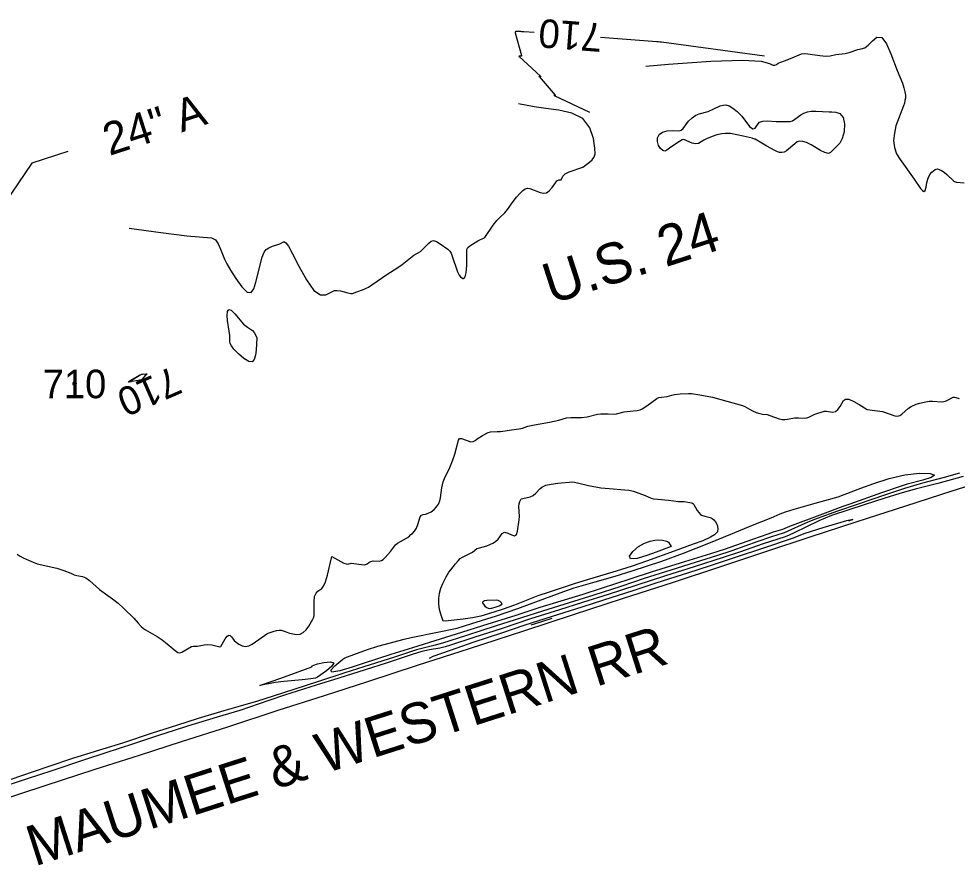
# Model space of a CAD drawing. Extents: x -468541894 to 3393103, y -306086142 to 1227927.
# Drawn here: x 1843544 to 1844629, y 537989 to 538967 of the extents above; entities that cross this region are included whole.
import ezdxf

# ---------------------------------------------------------------- set-up
doc = ezdxf.new("R2010")
doc.units = 0
for name, color, linetype in [('DT_X_Contour_Minor', 7, 'Continuous'), ('Level 14', 7, 'Continuous'), ('Level 19', 7, 'Continuous'), ('Level 40', 7, 'Continuous')]:
    doc.layers.add(name, color=color, linetype=linetype)

msp = doc.modelspace()

# ---------------------------------------------------------------- linework, layer by layer
at = {"layer": 'DT_X_Contour_Minor'}
for points in [[(1844140.1, 538951.4), (1844128.5, 538952.2), (1844127.3, 538952.3), (1844126.1, 538952.4), (1844124.8, 538952.5), (1844123.6, 538952.5), (1844119.6, 538952.7), (1844118.9, 538952.7), (1844118.4, 538952.4), (1844118.2, 538951.9), (1844118.3, 538951.2), (1844125.7, 538925), (1844125.8, 538924.5), (1844125.7, 538924.2), (1844125.4, 538924), (1844124.9, 538924), (1844123, 538924.2), (1844122.6, 538924.2), (1844122.5, 538924.1), (1844122.5, 538923.9), (1844122.8, 538923.7), (1844147.6, 538901.1), (1844147.8, 538900.8), (1844147.8, 538900.7), (1844147.7, 538900.6), (1844147.4, 538900.6), (1844146.1, 538900.8), (1844145.9, 538900.8), (1844145.8, 538900.7), (1844145.8, 538900.6), (1844145.9, 538900.4), (1844164.5, 538879.1), (1844164.6, 538878.9), (1844164.6, 538878.8), (1844164.5, 538878.8), (1844164.3, 538878.8), (1844163.4, 538878.9), (1844163.3, 538878.9), (1844163.2, 538878.9), (1844163.3, 538878.9), (1844163.4, 538878.8), (1844204.1, 538859.5)], [(1844406.7, 538924.2), (1844287.5, 538940.2), (1844287, 538940.3), (1844286.5, 538940.3), (1844286, 538940.4), (1844285.4, 538940.4), (1844283.7, 538940.5), (1844283.3, 538940.5), (1844282.9, 538940.6), (1844282.6, 538940.6), (1844282.2, 538940.6), (1844217.1, 538945.5)], [(1844269.3, 538912.4), (1844295.5, 538914.7), (1844344.6, 538918.3), (1844381.3, 538919.6), (1844402.7, 538918.3), (1844412.5, 538915.7), (1844416.3, 538913.7), (1844418.6, 538913.5), (1844420.6, 538914.5), (1844422.4, 538915.9), (1844424.3, 538916.9), (1844430.7, 538919), (1844441.4, 538923.3), (1844449.5, 538926.7), (1844452.4, 538927.1), (1844456.6, 538926.7), (1844470.7, 538924.7), (1844477.6, 538924.1), (1844482.6, 538924.5), (1844488.9, 538926.2), (1844499.8, 538927), (1844504.6, 538928.4), (1844514.3, 538931.9), (1844518.5, 538932.7), (1844522.4, 538933.9), (1844526.6, 538936.7), (1844531.4, 538941.8), (1844536.6, 538946.1), (1844542.2, 538945.8), (1844547.7, 538938.4), (1844552.8, 538926.8), (1844560.1, 538907.5), (1844566, 538892.9), (1844567.7, 538887.6), (1844568.9, 538882.8), (1844569.4, 538878.9), (1844569.4, 538875.6), (1844569, 538872.8), (1844568.3, 538869.9), (1844567.3, 538866.6), (1844558.6, 538843.5), (1844556.7, 538835.2), (1844555.9, 538826.7), (1844556.7, 538818.5), (1844559.3, 538811.2), (1844563.3, 538804.7), (1844579.7, 538782), (1844587.1, 538771), (1844589.1, 538768.7), (1844590.8, 538767.7), (1844592.3, 538768.9), (1844593.3, 538772.6), (1844594.4, 538777.9), (1844595.8, 538783.1), (1844597.9, 538787.1), (1844600.2, 538789.9), (1844603.9, 538792.9), (1844605.2, 538793.6), (1844606.7, 538793.7), (1844608.7, 538793.2), (1844611.3, 538792), (1844614.3, 538790.1), (1844617.4, 538787.2), (1844625, 538779.8), (1844626.4, 538779), (1844628.5, 538778.5), (1844637.5, 538777.8)], [(1844209.4, 538806.8), (1844210.7, 538810.8), (1844210.6, 538817.8), (1844209, 538828.8), (1844204.7, 538841.2), (1844196.6, 538851.9), (1844184, 538858.3), (1844168.8, 538861.5), (1844153.6, 538863.4), (1844140.1, 538865.5), (1844122.3, 538869.1)], [(1844395.8, 538828.2), (1844395.2, 538828.1), (1844392.3, 538829.1), (1844382.1, 538831.7), (1844374.4, 538833.3), (1844367.1, 538834.5), (1844361.5, 538834.8), (1844357.4, 538834.4), (1844351.5, 538833), (1844346.1, 538831.4), (1844339.6, 538828.7), (1844336.4, 538826.9), (1844333.3, 538824.9), (1844330.2, 538823.3), (1844326.8, 538822.7), (1844322.8, 538823.7), (1844313.2, 538827.6), (1844311.2, 538827.2), (1844305.1, 538823.4), (1844296.9, 538817.8), (1844293.8, 538815.6), (1844291.3, 538814.4), (1844289, 538814.9), (1844286.4, 538817.2), (1844284.1, 538821), (1844282.8, 538825.4), (1844283, 538829.8), (1844284.9, 538833.5), (1844288.6, 538836.3), (1844293.9, 538837.6), (1844299.8, 538838), (1844308.2, 538837.9), (1844310.3, 538838.5), (1844312.4, 538840.5), (1844318.8, 538848.8), (1844322.8, 538852.9), (1844327.1, 538855.8), (1844331.2, 538857.5), (1844341.4, 538860.3), (1844348.1, 538863.2), (1844355.3, 538866.5), (1844358.6, 538867.6), (1844361.9, 538867.8), (1844365.6, 538866.7), (1844370.1, 538864.1), (1844375.1, 538860), (1844380.2, 538854.6), (1844389.4, 538842.9), (1844392.9, 538840), (1844395.6, 538841), (1844398, 538844.3), (1844400.8, 538847.6), (1844404.7, 538849.1), (1844409.5, 538849.3), (1844420.2, 538848.7), (1844436.1, 538848.6), (1844438.8, 538849.4), (1844441.8, 538851.3), (1844448.5, 538856.3), (1844452.1, 538858.3), (1844456.1, 538859.8), (1844460.6, 538860.5), (1844465.9, 538860.6), (1844481.3, 538859.9), (1844484.5, 538859.9), (1844489, 538859.5), (1844493.7, 538857.7), (1844497.4, 538853.3), (1844499, 538845.8), (1844498.5, 538836.8), (1844496.5, 538828.9), (1844493.5, 538823.6), (1844485, 538815), (1844483, 538812.6), (1844480.4, 538811.6), (1844476.3, 538812.6), (1844471.3, 538815.2), (1844460.4, 538821.5), (1844455.3, 538824.1), (1844450.9, 538825.6), (1844447.5, 538825.9), (1844444.5, 538824.9), (1844441.7, 538822.8), (1844432.1, 538814.5), (1844429.3, 538813), (1844426.6, 538812.6), (1844424.1, 538812.8), (1844421.5, 538813.6), (1844418.5, 538815), (1844409.2, 538820.2), (1844395.8, 538828.2)], [(1843671.9, 538725.3), (1843708.5, 538720.3), (1843738.9, 538716.5), (1843767.1, 538713.9), (1843771.7, 538711.8), (1843775, 538707.3), (1843777.7, 538701.1), (1843782.3, 538689.5), (1843785.1, 538684), (1843789.3, 538676.8), (1843795.4, 538667.2), (1843802.3, 538657.6), (1843808.5, 538651.3), (1843813, 538650.7), (1843816, 538655), (1843818.5, 538662.9), (1843826, 538691.6), (1843828.1, 538697.3), (1843830.4, 538700.6), (1843833.5, 538702.6), (1843837.8, 538704.3), (1843846.4, 538707.2), (1843850.5, 538709.4), (1843851.7, 538709.6), (1843853.3, 538708.4), (1843856.1, 538704.3), (1843860.9, 538695.5), (1843868.2, 538681.2), (1843876.9, 538665.4), (1843885.7, 538653.1), (1843893.4, 538648), (1843899.5, 538648.3), (1843909.6, 538653.3), (1843912.4, 538653.3), (1843916.5, 538652.6), (1843924.7, 538650.5), (1843928.5, 538649.6), (1843930.1, 538649.8), (1843935.4, 538651.5), (1843941.9, 538654.1), (1843948.6, 538657.2), (1843952.6, 538659.8), (1843971.1, 538672.3), (1843981.5, 538679), (1843987.6, 538683.3), (1844001.2, 538693.9), (1844008.8, 538698.3), (1844015.3, 538704.8), (1844018.6, 538708), (1844021.2, 538710.1), (1844023.9, 538710.8), (1844027.2, 538709.8), (1844031.7, 538707.3), (1844040.4, 538700.9), (1844042.9, 538698.6), (1844044.3, 538696.4), (1844047.4, 538687.1), (1844049.6, 538680.5), (1844051.8, 538674.7), (1844053.7, 538670.9), (1844055.3, 538668.9), (1844057.7, 538667.2), (1844058.6, 538667), (1844059.5, 538667.5), (1844060.4, 538669.1), (1844061.2, 538672), (1844061.9, 538676.8), (1844062.3, 538683.4), (1844062.6, 538700.6), (1844063.4, 538702.9), (1844065.8, 538705), (1844075.2, 538710.4), (1844083.2, 538714.6), (1844092.9, 538728.8), (1844097.1, 538734), (1844100.6, 538737.6), (1844106.4, 538742.9), (1844109.4, 538746.7), (1844116.1, 538756.2), (1844120, 538761.1), (1844123.9, 538765.4), (1844127.3, 538768.7), (1844130, 538770.7), (1844132.5, 538771.4), (1844135.3, 538771), (1844147.3, 538766.4), (1844151, 538765.7), (1844154.5, 538766.2), (1844157.8, 538768.4), (1844161, 538772.3), (1844164, 538776.6), (1844166.6, 538779.9), (1844168.8, 538781.1), (1844171.6, 538781.3), (1844173.5, 538785.3), (1844176.2, 538787.9), (1844180.9, 538790.3), (1844196.5, 538795.6), (1844204.1, 538801.6), (1844207.2, 538804.2), (1844209.4, 538806.8)], [(1843819.6, 538598.3), (1843818.7, 538584.2), (1843818, 538578.3), (1843816.6, 538573.5), (1843814.3, 538570.8), (1843810.3, 538571), (1843804.6, 538574.6), (1843798.4, 538580.1), (1843793.2, 538585.4), (1843790.2, 538589.1), (1843789, 538591.7), (1843788.6, 538594.1), (1843788.3, 538601.1), (1843787.7, 538606.1), (1843785.8, 538618.3), (1843785.3, 538624.2), (1843785.6, 538628.8), (1843787.1, 538631.2), (1843790, 538630.5), (1843794.3, 538626.3), (1843804.4, 538614.4), (1843808.7, 538610.7), (1843814.8, 538606.8), (1843816.7, 538604.5), (1843818.1, 538602), (1843819.6, 538598.3)], [(1843673.4, 538549), (1843683.9, 538555.2), (1843684.2, 538555.4), (1843684.5, 538555.5), (1843684.8, 538555.7), (1843685.2, 538555.8), (1843686.2, 538556.3), (1843686.4, 538556.4), (1843686.6, 538556.5), (1843686.9, 538556.5), (1843687.1, 538556.6), (1843691.4, 538557), (1843692.1, 538557), (1843692.5, 538556.8), (1843692.4, 538556.4), (1843691.9, 538555.9), (1843690.5, 538554.4)], [(1843686.2, 538549.9), (1843679.8, 538548.6), (1843676.2, 538548.1), (1843674.4, 538548.5), (1843675.6, 538550), (1843682.3, 538554.2), (1843686.1, 538556.1), (1843689, 538556.7), (1843690.4, 538556.6), (1843691.1, 538556), (1843690.6, 538554.8), (1843687, 538550.8), (1843686.2, 538549.9)], [(1843607.5, 538546.9), (1843606.9, 538544.8), (1843606.9, 538544.5), (1843607, 538544.4), (1843607.1, 538544.3), (1843607.4, 538544.3), (1843608.3, 538544.3), (1843608.5, 538544.3), (1843608.7, 538544.3), (1843608.8, 538544.3), (1843609, 538544.2), (1843609.7, 538544.2), (1843609.9, 538544.2), (1843610, 538544.2), (1843610.1, 538544.3), (1843610.2, 538544.4), (1843611.2, 538545.5), (1843611.3, 538545.7), (1843611.3, 538545.9), (1843611.2, 538546.1), (1843611, 538546.2), (1843608.3, 538547.2), (1843608.2, 538547.2), (1843608.2, 538547.2), (1843608.1, 538547.2), (1843608, 538547.2), (1843607.7, 538547.1), (1843607.6, 538547.1), (1843607.6, 538547), (1843607.6, 538547), (1843607.5, 538546.9)], [(1843608.2, 538547.3), (1843610.2, 538546.4), (1843610.7, 538545.9), (1843610.8, 538545.4), (1843610, 538544.5), (1843609.1, 538544.2), (1843607.5, 538544.4), (1843607.2, 538544.7), (1843607.3, 538546), (1843607.9, 538547.2), (1843608.2, 538547.3)], [(1843674.7, 538547.5), (1843674, 538547.4), (1843672, 538547.1), (1843671.3, 538547.2), (1843671.7, 538547.9), (1843673.4, 538549)], [(1844213.4, 538510.2), (1844217.4, 538510.5), (1844225.8, 538510.4), (1844232.6, 538510.2), (1844235.4, 538510.4), (1844244.5, 538512.9), (1844254.8, 538514.1), (1844259.4, 538514.6), (1844262.7, 538515.3), (1844265.2, 538516.3), (1844270.7, 538519.9), (1844282.1, 538528.4), (1844284.5, 538529.5), (1844287.4, 538530), (1844293.9, 538530.6), (1844299.5, 538532.1), (1844302.4, 538532.9), (1844309.2, 538533.7), (1844318.6, 538534.2), (1844322.3, 538534), (1844331.9, 538532.4), (1844346.5, 538529.8), (1844362.9, 538525.4), (1844381.2, 538520.4), (1844384, 538519.1), (1844389.1, 538515.9), (1844392.8, 538514), (1844397.1, 538512.1), (1844401.1, 538510.8), (1844404.2, 538510.3), (1844409.6, 538509.8), (1844412.9, 538508.8), (1844423.7, 538504.8), (1844427, 538504.2), (1844430.1, 538504), (1844433.3, 538504.4), (1844441.3, 538505.9), (1844446, 538505.8), (1844452.6, 538505.7), (1844455.7, 538505.9), (1844458, 538506.6), (1844464.8, 538510), (1844475.6, 538513.8), (1844478.3, 538513.8), (1844485.1, 538512.6), (1844488.5, 538513.2), (1844491.4, 538515.5), (1844493.9, 538519), (1844497.8, 538525.8), (1844500.2, 538527.6), (1844504, 538527.4), (1844509.7, 538524.9), (1844516, 538521.4), (1844525.4, 538515.5), (1844542.9, 538513.1), (1844557.3, 538508.3), (1844560.5, 538508), (1844563.1, 538508.7), (1844565.3, 538510.2), (1844572.9, 538517.2), (1844576.1, 538519.1), (1844582.1, 538521.6), (1844586.2, 538523.1), (1844591.3, 538524.2), (1844597, 538525.1), (1844600.9, 538525.3), (1844611.4, 538524.6), (1844613.9, 538524.8), (1844616, 538525.3), (1844618.1, 538526.2), (1844624.6, 538529.7), (1844626.3, 538529.9), (1844627.9, 538529.5), (1844631.7, 538528.2)], [(1843798.9, 538244.2), (1843802.6, 538242.4), (1843806.5, 538241.6), (1843810.3, 538242.3), (1843814.1, 538244.1), (1843822, 538249.6), (1843831.1, 538256.2), (1843832.9, 538257.1), (1843838.5, 538258.9), (1843842.2, 538260), (1843845.5, 538260.6), (1843847.8, 538260.5), (1843852.4, 538258.8), (1843856.4, 538257.3), (1843861.1, 538256.1), (1843865.9, 538255.5), (1843869.9, 538256), (1843873.4, 538257.7), (1843876.5, 538260.7), (1843879.6, 538265), (1843884.3, 538273.2), (1843885.4, 538275.5), (1843885.8, 538277.4), (1843885.8, 538293.2), (1843886.5, 538299.3), (1843888.1, 538303.3), (1843890.2, 538305.5), (1843894.7, 538308.7), (1843896.8, 538311.5), (1843899, 538316.5), (1843901.3, 538324.2), (1843905.8, 538343.9), (1843906.2, 538345.5), (1843916.6, 538340), (1843920.4, 538338.1), (1843923, 538337.2), (1843924.7, 538336.9), (1843928.9, 538337.8), (1843931.8, 538337.6), (1843940.6, 538336.2), (1843944.6, 538336.1), (1843947.3, 538337.1), (1843949.1, 538338.7), (1843951.3, 538340), (1843954.3, 538340.5), (1843961.1, 538340.4), (1843963.6, 538340.9), (1843965.7, 538342.1), (1843968, 538344.3), (1843974, 538351.4), (1843979.9, 538359.3), (1843982.1, 538361), (1843989.2, 538365), (1843995.5, 538368.5), (1843997.8, 538370.9), (1843999.7, 538372.4), (1844002, 538374.8), (1844004.1, 538378.2), (1844005.8, 538382.7), (1844008.5, 538391.3), (1844010.1, 538393.3), (1844012.1, 538394.1), (1844014.6, 538394.7), (1844017.8, 538395.7), (1844021.2, 538397.4), (1844024.6, 538399.8), (1844027.5, 538402.9), (1844029.7, 538406.3), (1844031.3, 538409.9), (1844032.1, 538413.3), (1844033.6, 538425.2), (1844035.2, 538432.1), (1844036.8, 538435.9), (1844042.7, 538448.4), (1844045.8, 538456.1), (1844048.4, 538463.8), (1844052.8, 538480.2), (1844054.1, 538482), (1844056.3, 538482.1), (1844067.1, 538478.2), (1844069.9, 538478.5), (1844072.1, 538479.9), (1844074.5, 538481.8), (1844080.5, 538485.5), (1844087.2, 538489.1), (1844089.8, 538489.7), (1844097.5, 538490), (1844101.2, 538490.1), (1844106.8, 538490.9), (1844114, 538491.9), (1844123.1, 538493.1), (1844126.7, 538494), (1844133, 538496.2), (1844140.7, 538497.8), (1844158.2, 538500.9), (1844168.7, 538503.3), (1844177.5, 538505.8), (1844182.6, 538506.4), (1844195.1, 538506.4), (1844201.5, 538507.3), (1844213.4, 538510.2)], [(1844631.9, 538442), (1844614.1, 538436.8), (1844589.2, 538430.3), (1844568.3, 538424.1), (1844546.5, 538416.9), (1844513.8, 538405.8), (1844490.9, 538398.1), (1844467.4, 538389.5), (1844456.8, 538385.2), (1844429.4, 538373), (1844414.8, 538368.3), (1844399, 538362.9), (1844368.8, 538352.3), (1844351, 538346.3), (1844326.6, 538338.7), (1844298.3, 538330), (1844267.4, 538320.1), (1844240.3, 538311.1), (1844209.2, 538301), (1844180.7, 538292.2), (1844149.8, 538282.6), (1844125.5, 538274.7), (1844095.3, 538265), (1844061.9, 538254.2), (1844034.3, 538245.5), (1844025.8, 538243.1), (1844004.4, 538237.8), (1843978.7, 538229.3), (1843950.5, 538220.4), (1843921.4, 538211), (1843889.8, 538200.6), (1843863.6, 538192.4), (1843838.4, 538184), (1843820.6, 538178.2), (1843800.3, 538172.5), (1843781.4, 538167.3), (1843752, 538158.5), (1843726.6, 538150.4), (1843698.8, 538141.4), (1843664.4, 538130), (1843641.6, 538122.9), (1843607.6, 538112.4), (1843578.1, 538102.4), (1843546.4, 538091.6), (1843515, 538081)], [(1844497, 538403.5), (1844473.6, 538394.7), (1844435.6, 538380.2), (1844427.4, 538377), (1844416.7, 538373.7), (1844410.3, 538371.6), (1844392.6, 538365.3), (1844361.1, 538354), (1844344.1, 538348.7), (1844308.9, 538337.8), (1844275.7, 538327.6), (1844250.9, 538319.4), (1844217.9, 538308.5), (1844196.7, 538301.7), (1844162.4, 538291.3), (1844147, 538286.5), (1844119.1, 538277.6), (1844080.6, 538265.4), (1844056.1, 538257.6), (1844031.5, 538249.9), (1843999.6, 538240), (1843974.6, 538232.2), (1843942.5, 538221.9), (1843929.7, 538217.6), (1843915.8, 538213.5), (1843906.4, 538211.9), (1843905.3, 538214.4), (1843909.7, 538219.3), (1843918.9, 538226.8), (1843921.4, 538228.4), (1843931.7, 538232.4), (1843947.6, 538238.3), (1843959.6, 538242), (1843990, 538250), (1843998.1, 538252), (1844028.4, 538258.1), (1844051.2, 538262.9), (1844068.2, 538268.1), (1844096.6, 538277.1), (1844121.4, 538285.6), (1844145.2, 538294.3), (1844174.6, 538305.3), (1844186.4, 538309.4), (1844210.8, 538316.3), (1844233.8, 538322.9), (1844253.7, 538329.2), (1844287.9, 538340.4), (1844312.9, 538349.6), (1844342.3, 538360.9), (1844367.7, 538371.5), (1844392.8, 538381.7), (1844414.3, 538390.3), (1844424.8, 538395), (1844431, 538397.3), (1844440.8, 538400.4), (1844465.2, 538407.4), (1844491.7, 538414.8), (1844498.8, 538417.2), (1844518, 538424.5), (1844533, 538430), (1844550.6, 538435.7), (1844568.9, 538440.1), (1844585.7, 538442), (1844598.2, 538441.7), (1844603.3, 538439.8), (1844599.2, 538437), (1844589.6, 538434), (1844571.4, 538429.2), (1844564.5, 538427.1), (1844542, 538419.2), (1844505.1, 538406.2), (1844497, 538403.5)], [(1844636.2, 538438.2), (1844607.1, 538430.2), (1844582.3, 538423.9), (1844563.2, 538418.4), (1844544.4, 538412.5), (1844523, 538405.6), (1844484, 538392.9), (1844476.7, 538390.1), (1844469.3, 538386.7), (1844440.8, 538372.9), (1844435, 538370.3), (1844430.4, 538368.5), (1844404.9, 538360.1), (1844377.7, 538350.8), (1844358.9, 538344.5), (1844325.4, 538333.8), (1844292.2, 538323.3), (1844257.8, 538312.2), (1844225.9, 538301.8), (1844196.2, 538292.3), (1844169.6, 538284.1), (1844136.2, 538273.4), (1844103.2, 538262.5), (1844070.5, 538251.9), (1844043.7, 538243), (1844037.2, 538241.1), (1844031.4, 538239.8), (1844019.3, 538237.9), (1844010.6, 538235.9), (1843999.3, 538232.5), (1843969.3, 538222.3), (1843945, 538214.5), (1843914.4, 538204.8), (1843888.1, 538196.7), (1843851.8, 538185.5), (1843833.7, 538179.1), (1843800.1, 538167.5), (1843773.7, 538159.7), (1843739.4, 538149.4), (1843723.9, 538144.6), (1843707.1, 538139), (1843677.1, 538129), (1843643.9, 538118.2), (1843620.5, 538110.6), (1843582.8, 538097.9), (1843554.1, 538088.4), (1843518.7, 538076.9)], [(1844125.1, 538412.2), (1844127.2, 538412.8), (1844135.7, 538414.7), (1844139.2, 538416.3), (1844142.2, 538418.7), (1844146.9, 538424), (1844149.1, 538425.9), (1844151.3, 538427.1), (1844153.9, 538428.1), (1844160.1, 538429.4), (1844167.5, 538430.5), (1844184.9, 538431.8), (1844190.5, 538430.9), (1844203.2, 538427.9), (1844213.5, 538425.6), (1844217.4, 538425.1), (1844222.4, 538424.8), (1844249.6, 538422.2), (1844255, 538421), (1844261.2, 538419), (1844268.5, 538416), (1844275.4, 538413.1), (1844278.1, 538412.4), (1844283.3, 538411.9), (1844295.4, 538410.6), (1844307.3, 538409.2), (1844313.6, 538409.2), (1844322.6, 538407.8), (1844323.9, 538407), (1844325, 538405.6), (1844328.7, 538399), (1844332.5, 538394), (1844333.6, 538393.3), (1844337.7, 538392.2), (1844343.6, 538390.6), (1844346, 538389.6), (1844348, 538388), (1844349.9, 538385.6), (1844351.7, 538382.1), (1844352.8, 538378), (1844352.1, 538374), (1844348.9, 538370.6), (1844344.3, 538367.8), (1844335.4, 538363.9), (1844324, 538359.7), (1844302.1, 538351.9), (1844270.2, 538340.3), (1844253.4, 538334.5), (1844235, 538328.7), (1844204.1, 538319.4), (1844187.6, 538314.3), (1844157.6, 538304.5), (1844144.7, 538300), (1844117.5, 538289.5), (1844103.1, 538284.4), (1844087.6, 538279.3), (1844078.7, 538276.8), (1844068.8, 538274.7), (1844058.3, 538273.1), (1844040.9, 538271.3), (1844034.9, 538271), (1844034.5, 538272.2), (1844032.4, 538278.8), (1844031, 538284.4), (1844030.1, 538290.8), (1844030.1, 538297.2), (1844030.9, 538303.4), (1844032.5, 538309.2), (1844034.5, 538314.4), (1844038.6, 538322.3), (1844041.8, 538327.7), (1844044, 538330.4), (1844049.4, 538337.3), (1844052.3, 538340.8), (1844054.9, 538343.2), (1844057.3, 538344.8), (1844069, 538350.6), (1844074.1, 538354.8), (1844076.9, 538355.7), (1844085.6, 538358), (1844092.6, 538361.1), (1844095.7, 538362.9), (1844098.6, 538365.6), (1844103.2, 538372.3), (1844106.1, 538373.8), (1844110, 538372.6), (1844114.1, 538370.5), (1844117.7, 538369.4), (1844119.9, 538371.1), (1844121.1, 538374.9), (1844123.1, 538388), (1844123.2, 538392), (1844122.5, 538403.5), (1844123, 538406.6), (1844123.7, 538409.1), (1844125.1, 538412.2)], [(1844020.7, 538228.5), (1844019.2, 538228.2), (1844023.6, 538230.4), (1844043.4, 538237.5), (1844070.9, 538246.8), (1844102.9, 538257.5), (1844128.7, 538266.1), (1844161.3, 538276.7), (1844195.6, 538287.4), (1844220.8, 538295.5), (1844254.6, 538306.4), (1844282.4, 538315.4), (1844317.9, 538326.8), (1844344.3, 538335.4), (1844376.6, 538345.9), (1844402.2, 538354.4), (1844440, 538367.2), (1844446.7, 538370.1), (1844453.7, 538372.7), (1844474.5, 538379.3), (1844491.3, 538384.1), (1844501.9, 538387.1), (1844506.6, 538388.3), (1844506.7, 538388.2), (1844508.7, 538388.4), (1844503.8, 538386.4)], [(1844298.7, 538357.1), (1844281.4, 538350.8), (1844270.4, 538346.9), (1844259.3, 538343.5), (1844251.8, 538342.8), (1844250.6, 538345.9), (1844254.4, 538351.4), (1844260.9, 538357.1), (1844267.8, 538361), (1844274.4, 538363.3), (1844279.9, 538364.4), (1844283.9, 538364.8), (1844288.6, 538364.5), (1844293.2, 538363.3), (1844294.3, 538362.9), (1844295.4, 538362.1), (1844297.5, 538359.3), (1844298.7, 538357.1)], [(1843542.7, 538348.4), (1843546, 538346.1), (1843549.6, 538344), (1843558.4, 538340.1), (1843565.5, 538337.3), (1843588.5, 538332), (1843596.5, 538329.5), (1843604.8, 538326.2), (1843608.3, 538324.6), (1843611.6, 538323.5), (1843618.2, 538322.4), (1843621.9, 538320.9), (1843626, 538317.9), (1843637.6, 538307.3), (1843647.2, 538300.7), (1843652.8, 538296.7), (1843659.3, 538291.6), (1843666, 538285.7), (1843677.4, 538274.5), (1843682.6, 538268.7), (1843685.9, 538264.8), (1843688.7, 538262.3), (1843691.1, 538260.7), (1843699, 538256.2), (1843704.5, 538253.1), (1843710.3, 538249.3), (1843716.1, 538244.8), (1843725.3, 538236.9), (1843728.2, 538234.8), (1843730.5, 538234.4), (1843733.1, 538235.2), (1843744, 538241.4), (1843746.6, 538242.1), (1843751.2, 538242.1), (1843758.6, 538243.4), (1843763.1, 538243.8), (1843767.7, 538243.4), (1843776.9, 538241.2), (1843777.9, 538241.7), (1843783.1, 538250.6), (1843785.4, 538253.5), (1843787.2, 538254.6), (1843788.8, 538254.2), (1843790.2, 538252.8), (1843793.4, 538248.7), (1843795.8, 538246.4), (1843798.9, 538244.2)], [(1844080.9, 538292), (1844081, 538293.2), (1844081.6, 538294), (1844083, 538294.7), (1844085.5, 538295), (1844096.2, 538295.4), (1844098.2, 538295), (1844100.4, 538294), (1844102.1, 538292.5), (1844102.8, 538291), (1844102.2, 538289.7), (1844100.5, 538288.7), (1844094.8, 538286.6), (1844090.7, 538285.5), (1844089.1, 538285.3), (1844087.4, 538285.4), (1844085.7, 538286.1), (1844084.1, 538287.6), (1844082.7, 538289.3), (1844080.9, 538292)], [(1844137, 538266.6), (1844140.7, 538267.9), (1844161.1, 538274.4)], [(1843872.2, 538203), (1843850.7, 538201.1), (1843841, 538199.8), (1843823.2, 538196.3), (1843825.2, 538197.2), (1843847.5, 538204.9), (1843876.1, 538215.4), (1843883.2, 538218.1), (1843883.8, 538219.1), (1843885.4, 538220), (1843889.7, 538221.4), (1843897.1, 538223), (1843904.8, 538224), (1843908.7, 538222.8), (1843906.3, 538218.8), (1843900, 538213.4), (1843889.6, 538206), (1843887.5, 538204.9), (1843882.1, 538204.2), (1843872.2, 538203)]]:
    msp.add_lwpolyline(points, dxfattribs=at)
at = {"layer": 'Level 14'}
msp.add_lwpolyline([(1844675.8, 538437.8), (1844623.1, 538421.1), (1844569.5, 538404), (1844513.2, 538385.6), (1844459.1, 538367.9), (1844407.9, 538351.1), (1844355.8, 538333.6), (1844301, 538315.7), (1844241.9, 538296.6), (1844185.5, 538278.2), (1844127.8, 538259.4), (1844065, 538238.8), (1844004.9, 538219.8), (1843947.6, 538200.8), (1843897.6, 538184.7), (1843843.9, 538167.4), (1843785.9, 538148.5), (1843732.3, 538131.2), (1843683.8, 538115.7), (1843632.4, 538099.3), (1843574.4, 538080.4), (1843520.1, 538062.8)], dxfattribs=at)
at = {"layer": 'Level 40'}
for p, q in [((1843601.1, 538813.9), (1843559.6, 538800.4)), ((1843559.6, 538800.4), (1843198.3, 538270.3))]:
    msp.add_line(p, q, dxfattribs=at)

# ---------------------------------------------------------------- texts
at = {"layer": 'Level 19'}
for rotation, p in [(175.673, (1844220.2, 538961.8)), (203.5963, (1843722.5, 538566.2))]:
    msp.add_text('710', height=33, rotation=rotation, dxfattribs=at).set_placement(p)
msp.add_text('710', height=33, dxfattribs=at).set_placement((1843572, 538528.6))
at = {"layer": 'Level 40'}
for s, height, rotation, p in [('24" A', 37.5, 17.9864, (1843649.2, 538808.7)), ('U.S. 24', 46.8, 17.9864, (1844159.8, 538637)), ('MAUMEE & WESTERN RR', 46.8, 17.7425, (1843562.7, 537987.1))]:
    msp.add_text(s, height=height, rotation=rotation, dxfattribs=at).set_placement(p)

doc.saveas('drawing.dxf')
